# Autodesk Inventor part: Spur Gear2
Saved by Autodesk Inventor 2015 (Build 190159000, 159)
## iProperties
Created: 2014-06
Part Number: Spur Gear2
Material: Steel
Document SubType Name: Modeling
Designer: User
Categories: <?xml version="1.0" encoding="UTF-16"?> <MemberInstance><Categories><FamilyTemplate><FamilyTemplateParameter ValueType="xs:double" Id="1" ObjectReferenceKey="da
Density: 1 g/cm^3
Appearance: Steel
CustomPartVersion: 1
Author: User
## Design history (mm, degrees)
sketch "Sketch1"
  geometry: C1 r 8.198 at (0, 0)
  constraints: 1 centre point
  dimensions: "d0" = 16.39526 diameter of C1 (= da_da)
extrude "Extrusion1" new body sketch "Sketch1" distance "d1" = 4 (= da_b); taper "d2" = 0 deg
workplane "Work Plane2"
sketch "Sketch2"
  geometry: C1 r 8.198 at (0, 0) reference; C2 r 7.4 at (0, 0)
  constraints: 1 centre point, 1 coincident
  dimensions: "d3" = 14.8 diameter of C2 (= da_dw)
feature "Pitch Diameter" sketch "Sketch2" dims "d4" = 10, "d5" = 0
workplane "Work Plane8"
workplane "Work Plane9"
feature "Spur Gear" dims "da_b" = 4, "da_d" = 14.62056, "da_aw" = 14.8, "da_da" = 16.39526, "da_df" = 12.80474, "da_dw" = 14.8, angle "da_beta" = 40 deg, "da_lefttooth" = 0, "da_righttooth" = 10
body "Solid1"
body "Srf1"
other parameters: "d16" = 14.8 (= da_aw), "d17" = 0, "d34" = 2.24399 (computed from da_z), "d39" = 0, "d41" = 0, "d43" = 14.8 (= da_aw), "d46" = 14.8 (= da_aw), "d47" = 0, "d48" = 0
